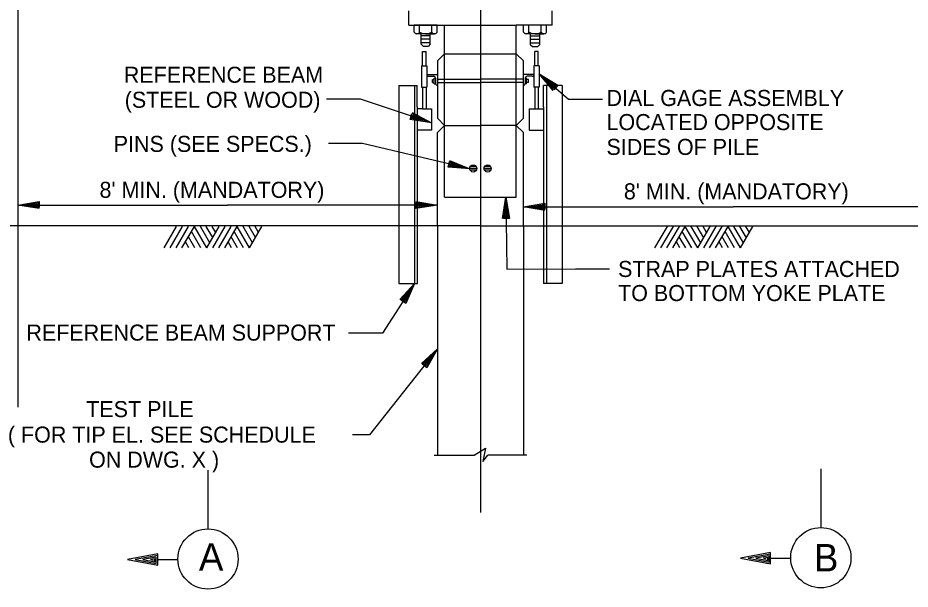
# Model space of a CAD drawing. Extents: x 22369.6 to 22413.6, y 22369.6 to 22403.6.
# Drawn here: x 22376.09 to 22383.87, y 22375.27 to 22380.25 of the extents above; entities that cross this region are included whole.
import ezdxf

# ---------------------------------------------------------------- set-up
doc = ezdxf.new("R2010")
doc.units = 0
for name, color, linetype in [('Level 1', 7, 'Continuous'), ('Level 2', 7, 'Continuous'), ('Level 3', 7, 'Continuous'), ('Level 4', 7, 'Continuous'), ('Level 7', 7, 'Continuous')]:
    doc.layers.add(name, color=color, linetype=linetype)

msp = doc.modelspace()

# ---------------------------------------------------------------- linework, layer by layer
at = {"layer": 'Level 1'}
for p, q in [((22380.1251, 22385.932), (22380.1251, 22375.9342)), ((22379.7476, 22380.1828), (22379.5476, 22380.1828)), ((22379.5476, 22380.1203), (22379.5476, 22380.1828)), ((22379.7242, 22380.1078), (22379.5711, 22380.1078)), ((22379.5944, 22380.1203), (22379.5944, 22380.1828)), ((22379.6476, 22380.1078), (22379.7242, 22380.1078)), ((22379.7007, 22380.1203), (22379.7007, 22380.1828)), ((22379.7476, 22380.1203), (22379.7476, 22380.1828)), ((22380.7015, 22380.1826), (22380.5015, 22380.1826)), ((22380.5015, 22380.1201), (22380.5015, 22380.1826)), ((22380.5483, 22380.1201), (22380.5483, 22380.1826)), ((22380.6546, 22380.1201), (22380.6546, 22380.1826)), ((22380.7015, 22380.1201), (22380.7015, 22380.1826)), ((22379.6094, 22380.0937), (22379.6876, 22380.0937)), ((22379.6094, 22380.0625), (22379.6876, 22380.0625)), ((22379.6094, 22380.0312), (22379.6876, 22380.0312)), ((22380.6781, 22380.1076), (22380.525, 22380.1076)), ((22380.5626, 22380.0904), (22380.6407, 22380.0904)), ((22380.5626, 22380.0591), (22380.6407, 22380.0591)), ((22380.6015, 22380.1076), (22380.6781, 22380.1076)), ((22380.5626, 22380.0279), (22380.6407, 22380.0279)), ((22380.6379, 22379.7592), (22380.6379, 22379.7592)), ((22380.6772, 22379.7252), (22380.6772, 22379.7252)), ((22379.6496, 22379.3485), (22379.6496, 22379.3485)), ((22379.699, 22379.3322), (22379.699, 22379.3322)), ((22379.9809, 22378.9428), (22379.9809, 22378.9428)), ((22380.0315, 22378.9308), (22380.0315, 22378.9308)), ((22380.3455, 22378.6837), (22380.3455, 22378.6837)), ((22380.3464, 22378.6318), (22380.3464, 22378.6318)), ((22376.0938, 22378.6146), (22377.9219, 22378.6146)), ((22376.0938, 22378.6146), (22376.0938, 22378.6146)), ((22376.1458, 22378.6146), (22376.1458, 22378.6146)), ((22379.7501, 22378.6146), (22377.9219, 22378.6146)), ((22379.6981, 22378.6146), (22379.6981, 22378.6146)), ((22379.7501, 22378.6146), (22379.7501, 22378.6146)), ((22380.5001, 22378.5989), (22382.3282, 22378.5989)), ((22380.5001, 22378.5989), (22380.5001, 22378.5989)), ((22380.5521, 22378.5989), (22380.5521, 22378.5989)), ((22384.1563, 22378.5989), (22382.3282, 22378.5989)), ((22377.368, 22378.2415), (22377.4762, 22378.429)), ((22377.42, 22378.2415), (22377.5282, 22378.429)), ((22377.472, 22378.2415), (22377.5802, 22378.429)), ((22377.5238, 22378.2415), (22377.6321, 22378.429)), ((22377.7403, 22378.2415), (22377.6321, 22378.429)), ((22377.7663, 22378.2865), (22377.6841, 22378.429)), ((22377.7923, 22378.3315), (22377.7361, 22378.429)), ((22377.7403, 22378.2415), (22377.8486, 22378.4288)), ((22377.8183, 22378.3765), (22377.7881, 22378.429)), ((22377.7923, 22378.2415), (22377.9007, 22378.429)), ((22377.8442, 22378.2415), (22377.9526, 22378.429)), ((22377.8962, 22378.2415), (22378.0046, 22378.429)), ((22378.1128, 22378.2415), (22378.0046, 22378.429)), ((22378.1388, 22378.2865), (22378.0566, 22378.429)), ((22378.1648, 22378.3315), (22378.1086, 22378.429)), ((22378.1128, 22378.2415), (22378.2212, 22378.429)), ((22378.1908, 22378.3765), (22378.1606, 22378.429)), ((22381.6463, 22378.2405), (22381.7546, 22378.428)), ((22381.6983, 22378.2405), (22381.8066, 22378.428)), ((22381.7503, 22378.2405), (22381.8586, 22378.428)), ((22381.8022, 22378.2405), (22381.9104, 22378.428)), ((22382.0187, 22378.2405), (22381.9104, 22378.428)), ((22382.0447, 22378.2855), (22381.9624, 22378.428)), ((22382.0707, 22378.3305), (22382.0144, 22378.428)), ((22382.0187, 22378.2405), (22382.1269, 22378.4279)), ((22382.0967, 22378.3755), (22382.0664, 22378.428)), ((22382.0707, 22378.2405), (22382.1791, 22378.428)), ((22382.1226, 22378.2405), (22382.2309, 22378.428)), ((22382.1746, 22378.2405), (22382.2829, 22378.428)), ((22382.3912, 22378.2405), (22382.2829, 22378.428)), ((22382.4172, 22378.2855), (22382.3349, 22378.428)), ((22382.4432, 22378.3305), (22382.3869, 22378.428)), ((22382.3912, 22378.2405), (22382.4996, 22378.428)), ((22382.4692, 22378.3755), (22382.4389, 22378.428)), ((22377.6363, 22378.2415), (22377.5801, 22378.339)), ((22377.6883, 22378.2415), (22377.6061, 22378.384)), ((22378.0088, 22378.2415), (22377.9526, 22378.339)), ((22378.0608, 22378.2415), (22377.9786, 22378.384)), ((22381.9147, 22378.2405), (22381.8584, 22378.338)), ((22381.9667, 22378.2405), (22381.8844, 22378.383)), ((22382.2872, 22378.2405), (22382.2309, 22378.338)), ((22382.3392, 22378.2405), (22382.2569, 22378.383)), ((22377.5845, 22378.2415), (22377.5542, 22378.294)), ((22377.957, 22378.2415), (22377.9267, 22378.294)), ((22381.8628, 22378.2405), (22381.8326, 22378.293)), ((22382.2353, 22378.2405), (22382.2051, 22378.293)), ((22379.5497, 22377.9322), (22379.5497, 22377.9322)), ((22379.5217, 22377.8884), (22379.5217, 22377.8884)), ((22379.7179, 22377.3214), (22379.7179, 22377.3214)), ((22379.7179, 22377.3214), (22379.7179, 22377.3214)), ((22379.7179, 22377.3214), (22379.7179, 22377.3214)), ((22379.7501, 22377.3622), (22379.7501, 22377.3622)), ((22379.7501, 22377.3622), (22379.7501, 22377.3622)), ((22379.7501, 22377.3622), (22379.7501, 22377.3622))]:
    msp.add_line(p, q, dxfattribs=at)
for points in [[(22380.6379, 22379.7592), (22380.8934, 22379.5378), (22381.1897, 22379.5378)], [(22380.7589, 22379.6133), (22380.6379, 22379.7592), (22380.7995, 22379.6602), (22380.7648, 22379.6201), (22380.6772, 22379.7252), (22380.7869, 22379.6579), (22380.7647, 22379.6322), (22380.715, 22379.6924), (22380.7743, 22379.6555), (22380.7652, 22379.645), (22380.7543, 22379.6584)], [(22379.699, 22379.3322), (22379.0801, 22379.5372), (22378.7838, 22379.5372)], [(22379.5312, 22379.4204), (22379.699, 22379.3322), (22379.5117, 22379.3616), (22379.5284, 22379.4119), (22379.6496, 22379.3485), (22379.5225, 22379.3685), (22379.5332, 22379.4008), (22379.6022, 22379.3642), (22379.5332, 22379.3755), (22379.5376, 22379.3888), (22379.5528, 22379.3806)], [(22380.0315, 22378.9308), (22379.0978, 22379.152), (22378.8014, 22379.152)], [(22379.8567, 22379.004), (22380.0315, 22378.9308), (22379.8424, 22378.9437), (22379.8546, 22378.9953), (22379.9809, 22378.9428), (22379.8525, 22378.9516), (22379.8603, 22378.9847), (22379.9323, 22378.9543), (22379.8626, 22378.9595), (22379.8658, 22378.9731), (22379.8817, 22378.9663)], [(22376.2808, 22378.5836), (22376.0938, 22378.6146), (22376.2808, 22378.6456), (22376.2808, 22378.5926), (22376.1458, 22378.6146), (22376.2728, 22378.6356), (22376.2728, 22378.6016), (22376.1958, 22378.6146), (22376.2648, 22378.6256), (22376.2648, 22378.6116), (22376.2478, 22378.6146)], [(22379.5631, 22378.6456), (22379.7501, 22378.6146), (22379.5631, 22378.5836), (22379.5631, 22378.6366), (22379.6981, 22378.6146), (22379.5711, 22378.5936), (22379.5711, 22378.6276), (22379.6481, 22378.6146), (22379.5791, 22378.6036), (22379.5791, 22378.6176), (22379.5961, 22378.6146)], [(22380.3177, 22378.4962), (22380.3455, 22378.6837), (22380.3797, 22378.4973), (22380.3267, 22378.4964), (22380.3464, 22378.6318), (22380.3695, 22378.5051), (22380.3355, 22378.5046), (22380.3472, 22378.5818), (22380.3594, 22378.513), (22380.3454, 22378.5127), (22380.3481, 22378.5298)], [(22380.3455, 22378.6837), (22380.3561, 22378.0561), (22380.9534, 22378.0583), (22381.2498, 22378.0583)], [(22380.6871, 22378.5679), (22380.5001, 22378.5989), (22380.6871, 22378.6299), (22380.6871, 22378.5769), (22380.5521, 22378.5989), (22380.6791, 22378.6199), (22380.6791, 22378.5859), (22380.6021, 22378.5989), (22380.6711, 22378.6099), (22380.6711, 22378.5959), (22380.6541, 22378.5989)], [(22379.5497, 22377.9322), (22379.2715, 22377.4974), (22378.9751, 22377.4974)], [(22379.4228, 22377.7914), (22379.5497, 22377.9322), (22379.475, 22377.758), (22379.4304, 22377.7866), (22379.5217, 22377.8884), (22379.4709, 22377.7701), (22379.4423, 22377.7885), (22379.4947, 22377.8463), (22379.4668, 22377.7823), (22379.455, 22377.7898), (22379.4667, 22377.8025)], [(22379.7501, 22377.3622), (22379.1583, 22376.6112), (22379.0113, 22376.6112)], [(22379.61, 22377.2345), (22379.7501, 22377.3622), (22379.6587, 22377.1962), (22379.6171, 22377.229), (22379.7179, 22377.3214), (22379.6558, 22377.2086), (22379.6291, 22377.2297), (22379.687, 22377.2821), (22379.6529, 22377.2211), (22379.6419, 22377.2298), (22379.6548, 22377.2413)]]:
    msp.add_lwpolyline(points, dxfattribs=at)
for centre, radius, start, end in [((22379.571, 22380.136), 0.0282, 213.88946, 326.11055), ((22379.6476, 22380.2267), 0.119, 243.46764, 296.53236), ((22379.7242, 22380.1361), 0.0283, 214.00566, 325.99434), ((22380.5249, 22380.1359), 0.0282, 213.90004, 326.09996), ((22380.6015, 22380.2266), 0.119, 243.46764, 296.53236), ((22380.6781, 22380.1359), 0.0283, 213.99513, 326.00487)]:
    msp.add_arc(centre, radius, start, end, dxfattribs=at)
at = {"layer": 'Level 2'}
for p, q in [((22379.6094, 22380.0156), (22379.6094, 22380.1066)), ((22379.6876, 22380.0156), (22379.6876, 22380.1076)), ((22380.5626, 22380.0122), (22380.5626, 22380.1052)), ((22380.6407, 22380.1051), (22380.6407, 22380.0122)), ((22379.6094, 22380.0156), (22379.6251, 22380)), ((22379.6209, 22379.8289), (22379.6209, 22379.9539)), ((22379.6209, 22379.9539), (22379.6521, 22379.9539)), ((22379.6251, 22380), (22379.6719, 22380)), ((22379.6521, 22379.8289), (22379.6521, 22379.9539)), ((22379.6876, 22380.0156), (22379.6719, 22380)), ((22380.5626, 22380.0122), (22380.5782, 22379.9966)), ((22380.5782, 22379.9966), (22380.6251, 22379.9966)), ((22380.598, 22379.8289), (22380.598, 22379.9539)), ((22380.6292, 22379.9539), (22380.598, 22379.9539)), ((22380.6407, 22380.0122), (22380.6251, 22379.9966)), ((22380.6292, 22379.8289), (22380.6292, 22379.9539)), ((22379.7501, 22379.8712), (22379.8126, 22379.9337)), ((22379.8126, 22379.9337), (22380.4376, 22379.9337)), ((22380.4376, 22379.9337), (22380.5001, 22379.8712)), ((22379.6123, 22379.8289), (22379.6123, 22379.6414)), ((22379.6123, 22379.8289), (22379.6591, 22379.8289)), ((22379.6591, 22379.8289), (22379.6591, 22379.6414)), ((22379.7501, 22379.8712), (22379.7501, 22379.3712)), ((22380.5001, 22379.3712), (22380.5001, 22379.8712)), ((22380.591, 22379.8289), (22380.591, 22379.6414)), ((22380.6379, 22379.8289), (22380.591, 22379.8289)), ((22380.6379, 22379.8289), (22380.6379, 22379.6414)), ((22379.6563, 22379.7526), (22379.6563, 22379.7526)), ((22379.6591, 22379.7526), (22379.7501, 22379.7526)), ((22379.6719, 22379.7369), (22379.7188, 22379.7369)), ((22379.7225, 22379.6715), (22379.7225, 22379.7217)), ((22379.7225, 22379.7217), (22379.7344, 22379.7217)), ((22379.7344, 22379.7213), (22379.7344, 22379.6744)), ((22380.591, 22379.7526), (22380.5001, 22379.7526)), ((22380.5276, 22379.7217), (22380.5157, 22379.7217)), ((22380.5157, 22379.7213), (22380.5157, 22379.6744)), ((22380.5276, 22379.6715), (22380.5276, 22379.7217)), ((22380.5782, 22379.7369), (22380.5313, 22379.7369)), ((22380.5938, 22379.7526), (22380.5938, 22379.7526)), ((22379.414, 22379.657), (22379.414, 22378.4322)), ((22379.414, 22379.657), (22379.574, 22379.657)), ((22379.55, 22379.657), (22379.55, 22377.9322)), ((22379.574, 22379.4695), (22379.574, 22379.657)), ((22379.6123, 22379.6414), (22379.6591, 22379.6414)), ((22379.6209, 22379.6414), (22379.6209, 22379.4539)), ((22379.6521, 22379.6414), (22379.6521, 22379.4539)), ((22379.7067, 22379.71), (22379.7225, 22379.71)), ((22379.7067, 22379.6822), (22379.7067, 22379.71)), ((22379.7067, 22379.6822), (22379.7225, 22379.6822)), ((22379.7225, 22379.6715), (22379.7344, 22379.6715)), ((22379.7501, 22379.7115), (22380.1251, 22379.7115)), ((22379.7501, 22379.6837), (22380.1251, 22379.6837)), ((22380.5001, 22379.7115), (22380.1251, 22379.7115)), ((22380.5001, 22379.6837), (22380.1251, 22379.6837)), ((22380.5276, 22379.6715), (22380.5157, 22379.6715)), ((22380.5434, 22379.71), (22380.5276, 22379.71)), ((22380.5434, 22379.6822), (22380.5276, 22379.6822)), ((22380.5434, 22379.6822), (22380.5434, 22379.71)), ((22380.6379, 22379.6414), (22380.591, 22379.6414)), ((22380.598, 22379.6414), (22380.598, 22379.4539)), ((22380.6292, 22379.6414), (22380.6292, 22379.4539)), ((22380.8361, 22379.657), (22380.6761, 22379.657)), ((22380.6761, 22379.4695), (22380.6761, 22379.657)), ((22380.7001, 22379.657), (22380.7001, 22377.9322)), ((22380.8361, 22379.657), (22380.8361, 22378.4322)), ((22379.574, 22379.4695), (22379.574, 22379.282)), ((22379.6209, 22379.4539), (22379.574, 22379.4539)), ((22379.6209, 22379.4539), (22379.699, 22379.4539)), ((22379.699, 22379.4539), (22379.699, 22379.2664)), ((22380.5511, 22379.4539), (22380.598, 22379.4539)), ((22380.5511, 22379.4539), (22380.5511, 22379.2664)), ((22380.598, 22379.4539), (22380.6292, 22379.4539)), ((22380.6292, 22379.4539), (22380.6761, 22379.4539)), ((22380.6761, 22379.4695), (22380.6761, 22379.282)), ((22379.7501, 22379.3712), (22379.8126, 22379.3087)), ((22380.5001, 22379.3712), (22380.4376, 22379.3087)), ((22379.574, 22379.282), (22379.574, 22378.4322)), ((22379.699, 22379.2664), (22379.574, 22379.2664)), ((22379.7501, 22379.2462), (22379.8126, 22379.3087)), ((22379.8126, 22379.3087), (22380.1251, 22379.3087)), ((22380.4376, 22379.3087), (22380.1251, 22379.3087)), ((22380.5001, 22379.2462), (22380.4376, 22379.3087)), ((22380.5511, 22379.2664), (22380.6761, 22379.2664)), ((22380.6761, 22379.282), (22380.6761, 22378.4322)), ((22379.7501, 22378.4337), (22379.7501, 22379.2462)), ((22380.5001, 22378.4337), (22380.5001, 22379.2462)), ((22380.0889, 22378.9495), (22380.0363, 22378.9495)), ((22380.2136, 22378.9495), (22380.1611, 22378.9495)), ((22380.0937, 22378.9339), (22380.0318, 22378.9339)), ((22380.0892, 22378.9182), (22380.0358, 22378.9182)), ((22380.219, 22378.9339), (22380.1569, 22378.9339)), ((22380.2142, 22378.9182), (22380.1606, 22378.9182)), ((22380.1251, 22378.4337), (22372.56, 22378.4337)), ((22376.0938, 22378.4337), (22376.0938, 22376.8528)), ((22379.414, 22378.4322), (22379.414, 22377.9322)), ((22379.574, 22378.4322), (22379.574, 22377.9322)), ((22379.7501, 22378.4337), (22379.7501, 22376.4337)), ((22380.1251, 22378.4337), (22387.6902, 22378.4337)), ((22380.5001, 22378.4337), (22380.5001, 22376.4337)), ((22380.6761, 22378.4322), (22380.6761, 22377.9322)), ((22380.8361, 22378.4322), (22380.8361, 22377.9322)), ((22379.414, 22377.9322), (22379.5771, 22377.9322)), ((22380.8361, 22377.9322), (22380.6761, 22377.9322)), ((22380.0708, 22376.4337), (22380.1692, 22376.4953)), ((22380.1692, 22376.4953), (22380.1472, 22376.3811)), ((22379.7209, 22376.4337), (22380.0708, 22376.4337)), ((22380.1472, 22376.3811), (22380.1902, 22376.4337)), ((22380.5292, 22376.4337), (22380.1902, 22376.4337))]:
    msp.add_line(p, q, dxfattribs=at)
for centre in [(22380.0626, 22378.9337), (22380.1876, 22378.9337)]:
    msp.add_circle(centre, 0.0312, dxfattribs=at)
for centre, start, end in [((22379.6719, 22379.7525), 214.94568, 270.1466), ((22379.7188, 22379.7213), 0.02086, 89.86443), ((22380.5314, 22379.7213), 90.16262, 179.91382), ((22380.5783, 22379.7525), 269.81537, 325.0542), ((22379.75, 22379.6744), 179.82563, 270.47914), ((22380.5001, 22379.6744), 270.13556, 359.97913)]:
    msp.add_arc(centre, 0.0156, start, end, dxfattribs=at)
at = {"layer": 'Level 3'}
for p, q in [((22377.7504, 22376.3031), (22377.7504, 22375.7869)), ((22383.0916, 22376.3146), (22383.0916, 22375.7983)), ((22377.3129, 22375.5247), (22377.4879, 22375.5247)), ((22382.6541, 22375.5362), (22382.8291, 22375.5362))]:
    msp.add_line(p, q, dxfattribs=at)
for points in [[(22377.3129, 22375.5615), (22377.3129, 22375.5746), (22377.0504, 22375.5247), (22377.3129, 22375.4757), (22377.3129, 22375.5615), (22377.1174, 22375.5256), (22377.3003, 22375.4906), (22377.3003, 22375.5471), (22377.1834, 22375.5256), (22377.2881, 22375.506), (22377.2881, 22375.5322), (22377.2504, 22375.5256), (22377.2753, 22375.5209)], [(22382.6541, 22375.573), (22382.6541, 22375.5861), (22382.3916, 22375.5362), (22382.6541, 22375.4872), (22382.6541, 22375.573), (22382.4586, 22375.5371), (22382.6415, 22375.5021), (22382.6415, 22375.5586), (22382.5246, 22375.5371), (22382.6292, 22375.5175), (22382.6292, 22375.5437), (22382.5916, 22375.5371), (22382.6165, 22375.5323)]]:
    msp.add_lwpolyline(points, dxfattribs=at)
for centre in [(22377.7505, 22375.5298), (22383.0917, 22375.5413)]:
    msp.add_circle(centre, 0.2625, dxfattribs=at)
at = {"layer": 'Level 7'}
for p, q in [((22376.0938, 22380.7462), (22376.0938, 22378.4337)), ((22379.5001, 22380.1837), (22379.5001, 22380.3087)), ((22380.7501, 22380.1837), (22380.7501, 22380.3087)), ((22379.5001, 22380.1837), (22379.8126, 22380.1837)), ((22379.8126, 22378.6837), (22379.8126, 22380.1837)), ((22379.8126, 22380.1837), (22380.4376, 22380.1837)), ((22380.4376, 22378.6837), (22380.4376, 22380.1837)), ((22380.7501, 22380.1837), (22380.4376, 22380.1837)), ((22379.8126, 22378.6837), (22380.4376, 22378.6837))]:
    msp.add_line(p, q, dxfattribs=at)

# ---------------------------------------------------------------- texts
at = {"layer": 'Level 3'}
for s, p in [('A', (22377.6712, 22375.4282)), ('B', (22383.0306, 22375.4214))]:
    msp.add_text(s, height=0.2398, dxfattribs=at).set_placement(p)
at = {"layer": 'Level 4'}
for s, p in [('REFERENCE BEAM', (22377.0169, 22379.6801)), ('(STEEL OR WOOD)', (22377.0249, 22379.4624)), ('DIAL GAGE ASSEMBLY', (22381.2236, 22379.4779)), ('LOCATED OPPOSITE', (22381.2236, 22379.2679)), ('PINS (SEE SPECS.)', (22376.9291, 22379.0777)), ('SIDES OF PILE', (22381.2236, 22379.0514)), ("8' MIN. (MANDATORY)", (22376.8052, 22378.6776)), ("8' MIN. (MANDATORY)", (22381.3751, 22378.6641)), ('STRAP PLATES ATTACHED', (22381.3248, 22377.9877)), ('TO BOTTOM YOKE PLATE', (22381.3248, 22377.7777)), ('REFERENCE BEAM SUPPORT', (22376.1681, 22377.4332)), ('TEST PILE', (22376.6897, 22376.7664)), ('( FOR TIP EL. SEE SCHEDULE', (22376.0067, 22376.5442)), ('ON DWG. X )', (22376.7143, 22376.3261))]:
    msp.add_text(s, height=0.14, dxfattribs=at).set_placement(p)

doc.saveas('drawing.dxf')
